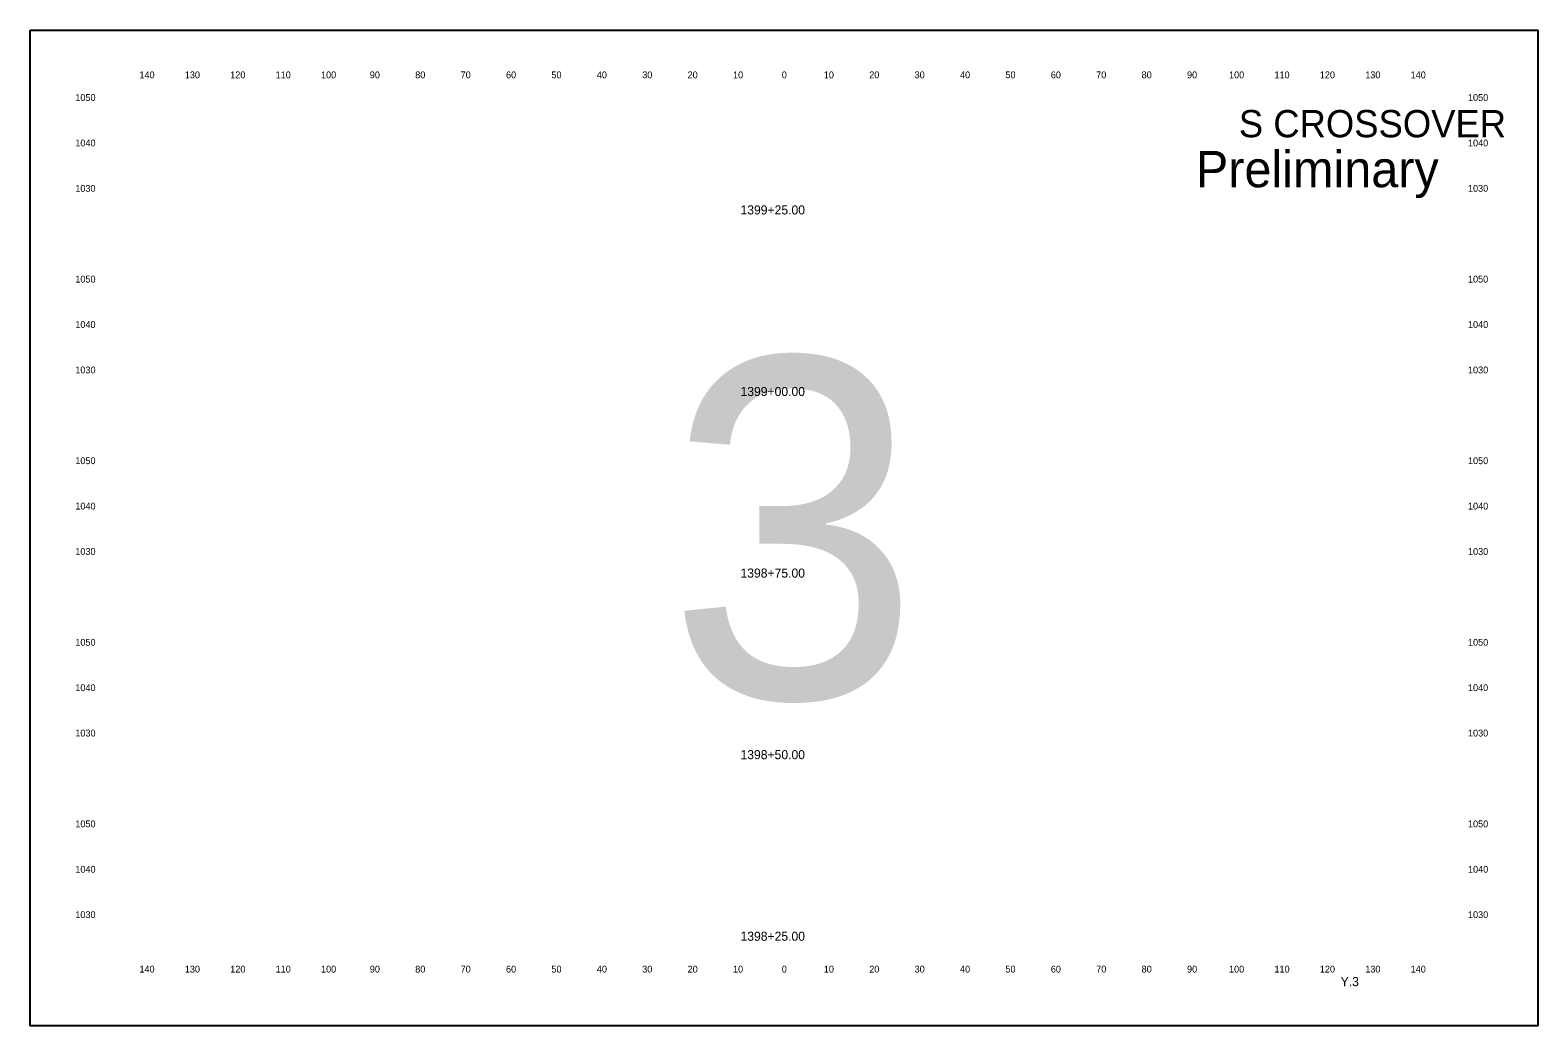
# Model space of a CAD drawing. Extents: x 10123 to 14768, y 9730 to 9950.
# Drawn here: x 10843.2 to 11175.3, y 9730.3 to 9949.6 of the extents above; entities that cross this region are included whole.
import ezdxf

# ---------------------------------------------------------------- set-up
doc = ezdxf.new("R2010")
doc.units = 0
for name, color, linetype in [('dsnTextCpn', 7, 'Continuous'), ('dsnTextCpnTitleSheetLocDesc', 7, 'Continuous'), ('dsnTextCpnTitleSheetPIN', 7, 'Continuous'), ('dsnTextCpnTitleSheetWorkType', 7, 'Continuous')]:
    doc.layers.add(name, color=color, linetype=linetype)

msp = doc.modelspace()

# ---------------------------------------------------------------- linework, layer by layer
at = {"layer": 'dsnTextCpnTitleSheetWorkType'}
msp.add_lwpolyline([(10843.21, 9949.6), (11175.29, 9949.6), (11175.29, 9730.26), (10843.21, 9730.26)], close=True, dxfattribs=at)

# ---------------------------------------------------------------- texts
at = {"layer": 'dsnTextCpn'}
for s, height, p in [('140', 1.5, (10867.27, 9939)), ('130', 1.5, (10877.27, 9939)), ('120', 1.5, (10887.27, 9939)), ('110', 1.5, (10897.27, 9939)), ('100', 1.5, (10907.27, 9939)), ('90', 1.5, (10918.02, 9939)), ('80', 1.5, (10928.02, 9939)), ('70', 1.5, (10938.02, 9939)), ('60', 1.5, (10948.02, 9939)), ('50', 1.5, (10958.02, 9939)), ('40', 1.5, (10968.02, 9939)), ('30', 1.5, (10978.02, 9939)), ('20', 1.5, (10988.02, 9939)), ('10', 1.5, (10998.02, 9939)), ('0', 1.5, (11008.76, 9939)), ('0', 1.5, (11008.76, 9939)), ('10', 1.5, (11018.02, 9939)), ('20', 1.5, (11028.02, 9939)), ('30', 1.5, (11038.02, 9939)), ('40', 1.5, (11048.02, 9939)), ('50', 1.5, (11058.02, 9939)), ('60', 1.5, (11068.02, 9939)), ('70', 1.5, (11078.02, 9939)), ('80', 1.5, (11088.02, 9939)), ('90', 1.5, (11098.02, 9939)), ('100', 1.5, (11107.27, 9939)), ('110', 1.5, (11117.27, 9939)), ('120', 1.5, (11127.27, 9939)), ('130', 1.5, (11137.27, 9939)), ('140', 1.5, (11147.27, 9939)), ('1050', 1.5, (10853.15, 9934)), ('1050', 1.5, (11159.9, 9934)), ('S CROSSOVER', 6, (11109.44, 9926)), ('1040', 1.5, (10853.15, 9924)), ('1040', 1.5, (11159.9, 9924)), ('1030', 1.5, (10853.15, 9914)), ('1030', 1.5, (11159.9, 9914)), ('1399+25.00', 2, (10999.67, 9909)), ('1050', 1.5, (10853.15, 9894)), ('1050', 1.5, (11159.9, 9894)), ('1040', 1.5, (10853.15, 9884)), ('1040', 1.5, (11159.9, 9884)), ('1030', 1.5, (10853.15, 9874)), ('1030', 1.5, (11159.9, 9874)), ('1399+00.00', 2, (10999.67, 9869)), ('1050', 1.5, (10853.15, 9854)), ('1050', 1.5, (11159.9, 9854)), ('1040', 1.5, (10853.15, 9844)), ('1040', 1.5, (11159.9, 9844)), ('1030', 1.5, (10853.15, 9834)), ('1030', 1.5, (11159.9, 9834)), ('1398+75.00', 2, (10999.67, 9829)), ('1050', 1.5, (10853.15, 9814)), ('1050', 1.5, (11159.9, 9814)), ('1040', 1.5, (10853.15, 9804)), ('1040', 1.5, (11159.9, 9804)), ('1030', 1.5, (10853.15, 9794)), ('1030', 1.5, (11159.9, 9794)), ('1398+50.00', 2, (10999.67, 9789)), ('1050', 1.5, (10853.15, 9774)), ('1050', 1.5, (11159.9, 9774)), ('1040', 1.5, (10853.15, 9764)), ('1040', 1.5, (11159.9, 9764)), ('1030', 1.5, (10853.15, 9754)), ('1030', 1.5, (11159.9, 9754)), ('1398+25.00', 2, (10999.67, 9749)), ('140', 1.5, (10867.27, 9742)), ('130', 1.5, (10877.27, 9742)), ('120', 1.5, (10887.27, 9742)), ('110', 1.5, (10897.27, 9742)), ('100', 1.5, (10907.27, 9742)), ('90', 1.5, (10918.02, 9742)), ('80', 1.5, (10928.02, 9742)), ('70', 1.5, (10938.02, 9742)), ('60', 1.5, (10948.02, 9742)), ('50', 1.5, (10958.02, 9742)), ('40', 1.5, (10968.02, 9742)), ('30', 1.5, (10978.02, 9742)), ('20', 1.5, (10988.02, 9742)), ('10', 1.5, (10998.02, 9742)), ('0', 1.5, (11008.76, 9742)), ('0', 1.5, (11008.76, 9742)), ('10', 1.5, (11018.02, 9742)), ('20', 1.5, (11028.02, 9742)), ('30', 1.5, (11038.02, 9742)), ('40', 1.5, (11048.02, 9742)), ('50', 1.5, (11058.02, 9742)), ('60', 1.5, (11068.02, 9742)), ('70', 1.5, (11078.02, 9742)), ('80', 1.5, (11088.02, 9742)), ('90', 1.5, (11098.02, 9742)), ('100', 1.5, (11107.27, 9742)), ('110', 1.5, (11117.27, 9742)), ('120', 1.5, (11127.27, 9742)), ('130', 1.5, (11137.27, 9742)), ('140', 1.5, (11147.27, 9742))]:
    msp.add_text(s, height=height, dxfattribs=at).set_placement(p)
at = {"layer": 'dsnTextCpnTitleSheetLocDesc'}
msp.add_text('Preliminary', height=8, dxfattribs=at).set_placement((11099.97, 9915))
at = {"layer": 'dsnTextCpnTitleSheetPIN'}
msp.add_text('Y.3', height=2, dxfattribs=at).set_placement((11131.86, 9739))
at = {"layer": 'dsnTextCpnTitleSheetWorkType'}
msp.add_text('3', height=75, dxfattribs=at).set_placement((10983.48, 9802.43))

doc.saveas('drawing.dxf')
